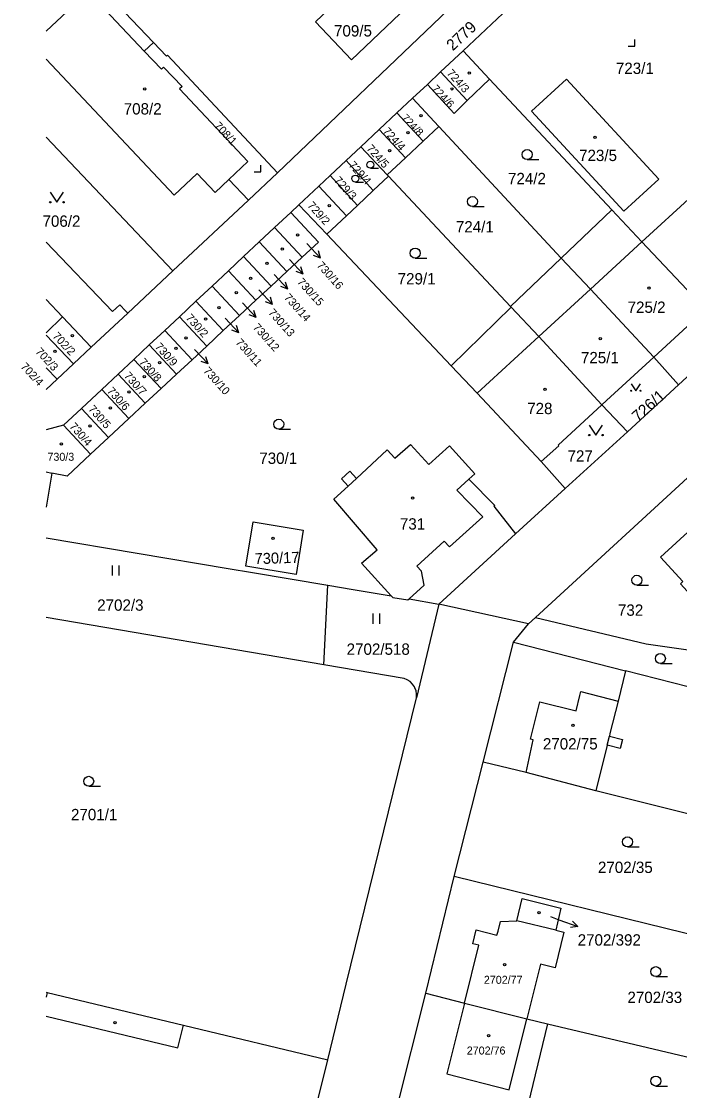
# Model space of a CAD drawing. Extents: x -496682 to -495776, y -1088797 to -1088018.
# Drawn here: x -496677.9 to -496579.2, y -1088379.3 to -1088218.9 of the extents above; entities that cross this region are included whole.
import ezdxf

# ---------------------------------------------------------------- set-up
doc = ezdxf.new("R2010")
doc.units = 0
for name, color, linetype in [('Hranice parcel', 7, 'Continuous'), ('Parcelní čísla', 7, 'Continuous'), ('Pop  PČ popisy', 7, 'Continuous'), ('Vnitřní kresba', 7, 'Continuous'), ('Značky budov', 7, 'Continuous'), ('Značky kultur', 7, 'Continuous')]:
    doc.layers.add(name, color=color, linetype=linetype)

msp = doc.modelspace()

# ---------------------------------------------------------------- linework, layer by layer
at = {"layer": 'Hranice parcel'}
for p, q in [((-496658.12, -1088222.07), (-496674.2, -1088205.13)), ((-496598.99, -1088211.34), (-496611.67, -1088223.3)), ((-496613.98, -1088217.23), (-496639.51, -1088241.62)), ((-496658.12, -1088222.07), (-496659.48, -1088223.35)), ((-496611.67, -1088223.3), (-496615.08, -1088226.47)), ((-496611.67, -1088223.3), (-496607.69, -1088227.55)), ((-496617.01, -1088228.38), (-496615.08, -1088226.47)), ((-496615.08, -1088226.47), (-496611.06, -1088230.75)), ((-496607.69, -1088227.55), (-496611.06, -1088230.75)), ((-496607.69, -1088227.55), (-496589.37, -1088247.15)), ((-496617.01, -1088228.38), (-496619.25, -1088230.42)), ((-496621.61, -1088232.63), (-496619.25, -1088230.42)), ((-496619.25, -1088230.42), (-496615.3, -1088234.67)), ((-496621.61, -1088232.63), (-496624.27, -1088235.13)), ((-496617.64, -1088236.86), (-496621.61, -1088232.63)), ((-496624.27, -1088235.13), (-496627.02, -1088237.7)), ((-496624.27, -1088235.13), (-496620.31, -1088239.36)), ((-496615.3, -1088234.67), (-496617.64, -1088236.86)), ((-496596.95, -1088254.39), (-496615.3, -1088234.67)), ((-496617.64, -1088236.86), (-496620.31, -1088239.36)), ((-496627.02, -1088237.7), (-496629.21, -1088239.75)), ((-496627.02, -1088237.7), (-496623.05, -1088241.94)), ((-496629.21, -1088239.75), (-496631.61, -1088242.01)), ((-496625.14, -1088244.28), (-496629.21, -1088239.75)), ((-496620.31, -1088239.36), (-496623.05, -1088241.94)), ((-496643.86, -1088245.72), (-496639.51, -1088241.62)), ((-496627.51, -1088246.52), (-496631.61, -1088242.01)), ((-496622.86, -1088242.14), (-496625.14, -1088244.28)), ((-496623.05, -1088241.94), (-496622.86, -1088242.14)), ((-496622.86, -1088242.14), (-496604.56, -1088261.65)), ((-496646.82, -1088242.63), (-496643.86, -1088245.72)), ((-496625.14, -1088244.28), (-496627.51, -1088246.52)), ((-496643.86, -1088245.72), (-496655.18, -1088256.3)), ((-496636.3, -1088246.41), (-496637.53, -1088247.57)), ((-496636.3, -1088246.41), (-496632.12, -1088250.83)), ((-496596.95, -1088254.39), (-496589.37, -1088247.15)), ((-496589.37, -1088247.15), (-496584.85, -1088251.98)), ((-496637.53, -1088247.57), (-496639.96, -1088249.83)), ((-496639.96, -1088249.83), (-496642.25, -1088251.98)), ((-496635.82, -1088254.27), (-496639.96, -1088249.83)), ((-496642.25, -1088251.98), (-496644.6, -1088254.18)), ((-496638.12, -1088256.41), (-496642.25, -1088251.98)), ((-496632.12, -1088250.83), (-496613.46, -1088270.55)), ((-496584.85, -1088251.98), (-496575.3, -1088262.11)), ((-496644.6, -1088254.18), (-496646.86, -1088256.3)), ((-496640.47, -1088258.61), (-496644.6, -1088254.18)), ((-496635.82, -1088254.27), (-496638.12, -1088256.41)), ((-496604.56, -1088261.65), (-496596.95, -1088254.39)), ((-496655.18, -1088256.3), (-496661.97, -1088262.66)), ((-496646.86, -1088256.3), (-496649.3, -1088258.59)), ((-496642.74, -1088260.72), (-496646.86, -1088256.3)), ((-496638.12, -1088256.41), (-496640.47, -1088258.61)), ((-496649.3, -1088258.59), (-496651.74, -1088260.88)), ((-496645.23, -1088263.03), (-496649.3, -1088258.59)), ((-496640.47, -1088258.61), (-496642.74, -1088260.72)), ((-496651.74, -1088260.88), (-496654.22, -1088263.2)), ((-496647.64, -1088265.28), (-496651.74, -1088260.88)), ((-496642.74, -1088260.72), (-496645.23, -1088263.03)), ((-496674.2, -1088265.6), (-496671.74, -1088263.22)), ((-496667.44, -1088267.77), (-496671.74, -1088263.22)), ((-496667.44, -1088267.77), (-496661.97, -1088262.66)), ((-496654.22, -1088263.2), (-496656.41, -1088265.25)), ((-496654.22, -1088263.2), (-496650.13, -1088267.6)), ((-496645.23, -1088263.03), (-496647.64, -1088265.28)), ((-496604.44, -1088261.78), (-496613.46, -1088270.55)), ((-496604.56, -1088261.65), (-496604.44, -1088261.78)), ((-496583.08, -1088269.26), (-496575.3, -1088262.11)), ((-496674.2, -1088265.98), (-496670.08, -1088270.24)), ((-496656.41, -1088265.25), (-496658.75, -1088267.43)), ((-496652.33, -1088269.64), (-496656.41, -1088265.25)), ((-496647.64, -1088265.28), (-496650.13, -1088267.6)), ((-496579.39, -1088273.39), (-496571.63, -1088266.25)), ((-496670.08, -1088270.24), (-496667.44, -1088267.77)), ((-496658.75, -1088267.43), (-496661.05, -1088269.59)), ((-496654.67, -1088271.82), (-496658.75, -1088267.43)), ((-496650.13, -1088267.6), (-496652.33, -1088269.64)), ((-496661.05, -1088269.59), (-496663.42, -1088271.81)), ((-496656.97, -1088273.96), (-496661.05, -1088269.59)), ((-496652.33, -1088269.64), (-496654.67, -1088271.82)), ((-496579.39, -1088273.39), (-496583.08, -1088269.26)), ((-496674.2, -1088270.84), (-496672.55, -1088272.55)), ((-496672.55, -1088272.55), (-496670.08, -1088270.24)), ((-496674.2, -1088274.09), (-496672.55, -1088272.55)), ((-496663.42, -1088271.81), (-496665.86, -1088274.1)), ((-496659.35, -1088276.18), (-496663.42, -1088271.81)), ((-496654.67, -1088271.82), (-496656.97, -1088273.96)), ((-496665.86, -1088274.1), (-496668.89, -1088276.94)), ((-496661.8, -1088278.46), (-496665.86, -1088274.1)), ((-496656.97, -1088273.96), (-496659.35, -1088276.18)), ((-496587.04, -1088280.45), (-496579.39, -1088273.39)), ((-496668.89, -1088276.94), (-496671.59, -1088279.46)), ((-496664.84, -1088281.29), (-496668.89, -1088276.94)), ((-496659.35, -1088276.18), (-496661.8, -1088278.46)), ((-496590.86, -1088276.42), (-496587.04, -1088280.45)), ((-496661.8, -1088278.46), (-496664.84, -1088281.29)), ((-496671.59, -1088279.46), (-496674.2, -1088280.16)), ((-496667.54, -1088283.8), (-496671.59, -1088279.46)), ((-496596.36, -1088288.95), (-496587.04, -1088280.45)), ((-496664.84, -1088281.29), (-496667.54, -1088283.8)), ((-496573.69, -1088283.35), (-496600.82, -1088308.29)), ((-496599.99, -1088284.92), (-496596.36, -1088288.95)), ((-496674.2, -1088286.47), (-496673.36, -1088286.64)), ((-496673.36, -1088286.64), (-496674.2, -1088291.77)), ((-496603.81, -1088295.77), (-496596.36, -1088288.95)), ((-496615.31, -1088306.29), (-496603.81, -1088295.77)), ((-496632.58, -1088315.39), (-496631.97, -1088303.45)), ((-496615.31, -1088306.29), (-496618.66, -1088320.33)), ((-496601.85, -1088309.24), (-496615.31, -1088306.29)), ((-496632.58, -1088315.39), (-496674.2, -1088308.3)), ((-496604.09, -1088312.01), (-496601.85, -1088309.24)), ((-496600.82, -1088308.29), (-496601.85, -1088309.24)), ((-496608.66, -1088330.02), (-496604.09, -1088312.01)), ((-496604.09, -1088312.01), (-496587.31, -1088316.31)), ((-496620.51, -1088317.45), (-496632.58, -1088315.39)), ((-496558.12, -1088323.79), (-496587.31, -1088316.31)), ((-496629.19, -1088363.28), (-496618.66, -1088320.33)), ((-496613.01, -1088347.16), (-496608.66, -1088330.02)), ((-496562.31, -1088341.65), (-496591.79, -1088334.31)), ((-496617.24, -1088364.65), (-496613.01, -1088347.16)), ((-496566.3, -1088358.61), (-496613.01, -1088347.16)), ((-496597.79, -1088355.21), (-496603.63, -1088353.81)), ((-496631.98, -1088374.63), (-496629.19, -1088363.28)), ((-496621.61, -1088381.96), (-496617.24, -1088364.65)), ((-496617.24, -1088364.65), (-496611.47, -1088366.13)), ((-496611.47, -1088366.13), (-496602.12, -1088368.5)), ((-496602.12, -1088368.5), (-496599.03, -1088369.24)), ((-496599.03, -1088369.24), (-496603.2, -1088386.53)), ((-496599.03, -1088369.24), (-496570.63, -1088376)), ((-496640.68, -1088410.13), (-496631.98, -1088374.63))]:
    msp.add_line(p, q, dxfattribs=at)
for points in [[(-496624.78, -1088213.12), (-496628.32, -1088216.5), (-496629.71, -1088215.04), (-496633.83, -1088218.99), (-496628.4, -1088224.66), (-496618, -1088214.72), (-496620.89, -1088211.75), (-496623.61, -1088214.35), (-496624.78, -1088213.12)], [(-496659.48, -1088223.35), (-496667.9, -1088214.43), (-496674.2, -1088220.39)], [(-496567.11, -1088219.32), (-496576.33, -1088227.9), (-496569.52, -1088235.23), (-496571.03, -1088236.8), (-496569.79, -1088238.16), (-496584.85, -1088251.98)], [(-496639.51, -1088241.62), (-496655.99, -1088223.95), (-496656.16, -1088224.12), (-496658.12, -1088222.07)], [(-496674.2, -1088224.58), (-496654.99, -1088244.96), (-496651.56, -1088241.73), (-496648.88, -1088244.57), (-496646.82, -1088242.63)], [(-496659.48, -1088223.35), (-496656.91, -1088226.08), (-496656.58, -1088225.77), (-496653.83, -1088228.68), (-496654.21, -1088229.04), (-496643.95, -1088239.92), (-496646.82, -1088242.63)], [(-496582.32, -1088242.55), (-496587.57, -1088247.38), (-496601.4, -1088232.39), (-496596.18, -1088227.58), (-496582.32, -1088242.55)], [(-496611.06, -1088230.75), (-496612.99, -1088232.74), (-496617.01, -1088228.38)], [(-496674.2, -1088236.29), (-496655.18, -1088256.3)], [(-496631.61, -1088242.01), (-496633.32, -1088243.62), (-496636.3, -1088246.41)], [(-496627.51, -1088246.52), (-496629.16, -1088248.07), (-496632.12, -1088250.83)], [(-496637.53, -1088247.57), (-496633.38, -1088252), (-496635.82, -1088254.27)], [(-496661.97, -1088262.66), (-496662.3, -1088262.31), (-496663.16, -1088261.41), (-496664.23, -1088262.43), (-496674.2, -1088251.99)], [(-496583.08, -1088269.26), (-496592.58, -1088259.08), (-496596.95, -1088254.39)], [(-496671.74, -1088263.22), (-496674.2, -1088260.62)], [(-496604.44, -1088261.78), (-496600.31, -1088266.18), (-496590.86, -1088276.42)], [(-496590.86, -1088276.42), (-496590.17, -1088275.78), (-496583.08, -1088269.26)], [(-496613.46, -1088270.55), (-496609.56, -1088274.67), (-496599.99, -1088284.92)], [(-496590.86, -1088276.42), (-496597.43, -1088282.45), (-496597.33, -1088282.57), (-496599.99, -1088284.92)], [(-496622.44, -1088305.06), (-496626.89, -1088300.16), (-496624.57, -1088298.15), (-496631.04, -1088290.58), (-496628.89, -1088288.59), (-496629.91, -1088287.49), (-496628.67, -1088286.35), (-496627.66, -1088287.45), (-496623.04, -1088283.17), (-496621.92, -1088284.39), (-496619.54, -1088282.35), (-496616.81, -1088285.36), (-496613.73, -1088282.57), (-496609.93, -1088286.75), (-496610.83, -1088287.57), (-496606.92, -1088291.49), (-496607.06, -1088291.61), (-496603.81, -1088295.77)], [(-496667.54, -1088283.8), (-496671.07, -1088287.09), (-496673.36, -1088286.64)], [(-496557.01, -1088316.13), (-496563.54, -1088302.9), (-496571.78, -1088310.53), (-496575.32, -1088306.66), (-496575.68, -1088306.99), (-496579.09, -1088303.24), (-496578.73, -1088302.91), (-496582.06, -1088299.26), (-496577.39, -1088294.94), (-496577.72, -1088294.58), (-496573.95, -1088291.1), (-496573.62, -1088291.45), (-496569.64, -1088287.77), (-496570.83, -1088286.2), (-496573.69, -1088283.35)], [(-496636.73, -1088301.87), (-496644.24, -1088300.6), (-496643.15, -1088293.97), (-496635.64, -1088295.22), (-496636.73, -1088301.87)], [(-496674.2, -1088296.34), (-496646.9, -1088300.94), (-496643.26, -1088301.55), (-496631.97, -1088303.45)], [(-496631.97, -1088303.45), (-496628.18, -1088304.09), (-496622.44, -1088305.06)], [(-496622.44, -1088305.06), (-496622.2, -1088305.33), (-496619.97, -1088305.68), (-496619.76, -1088305.49), (-496615.31, -1088306.29)], [(-496600.82, -1088308.29), (-496584.23, -1088312.23), (-496557.01, -1088316.13)], [(-496618.66, -1088320.33), (-496618.64, -1088319.82), (-496618.71, -1088319.31), (-496618.89, -1088318.83), (-496618.96, -1088318.7), (-496619.24, -1088318.28), (-496619.61, -1088317.92), (-496620.04, -1088317.64), (-496620.51, -1088317.45)], [(-496587.31, -1088316.31), (-496588.44, -1088320.85), (-496589.65, -1088325.71), (-496589.74, -1088326.09), (-496587.78, -1088326.58), (-496588.11, -1088327.93), (-496590.08, -1088327.44), (-496591.79, -1088334.31)], [(-496591.79, -1088334.31), (-496602.19, -1088331.54), (-496608.66, -1088330.02)], [(-496603.63, -1088353.81), (-496602.83, -1088350.47), (-496597, -1088351.88), (-496597.79, -1088355.21)], [(-496611.47, -1088366.13), (-496609.31, -1088357.47), (-496610.23, -1088357.24), (-496609.71, -1088355.17), (-496606.59, -1088355.94), (-496606.43, -1088355.33), (-496606.05, -1088353.9), (-496603.63, -1088353.81)], [(-496597.79, -1088355.21), (-496596.58, -1088355.5), (-496597.86, -1088360.83), (-496600.06, -1088360.3), (-496602.12, -1088368.5)], [(-496674.2, -1088364.5), (-496674.03, -1088364.55), (-496653.61, -1088369.44), (-496631.98, -1088374.63)]]:
    msp.add_lwpolyline(points, dxfattribs=at)
at = {"layer": 'Pop  PČ popisy'}
for p, q in [((-496635.11, -1088252.19), (-496633.06, -1088254.39)), ((-496633.06, -1088254.39), (-496633.38, -1088253.31)), ((-496637.72, -1088254.6), (-496635.67, -1088256.79)), ((-496633.06, -1088254.39), (-496634.11, -1088253.99)), ((-496635.67, -1088256.79), (-496636.72, -1088256.4)), ((-496635.67, -1088256.79), (-496635.99, -1088255.72)), ((-496640.02, -1088256.88), (-496637.97, -1088259.07)), ((-496637.97, -1088259.07), (-496638.29, -1088258)), ((-496642.31, -1088259.15), (-496640.26, -1088261.34)), ((-496637.97, -1088259.07), (-496639.02, -1088258.68)), ((-496644.77, -1088261.13), (-496642.72, -1088263.32)), ((-496640.26, -1088261.34), (-496641.31, -1088260.95)), ((-496640.26, -1088261.34), (-496640.58, -1088260.27)), ((-496642.72, -1088263.32), (-496643.77, -1088262.93)), ((-496642.72, -1088263.32), (-496643.04, -1088262.25)), ((-496647.37, -1088263.4), (-496645.32, -1088265.59)), ((-496645.32, -1088265.59), (-496645.64, -1088264.52)), ((-496645.32, -1088265.59), (-496646.37, -1088265.2)), ((-496651.97, -1088268.09), (-496649.92, -1088270.28)), ((-496649.92, -1088270.28), (-496650.24, -1088269.21)), ((-496649.92, -1088270.28), (-496650.97, -1088269.89)), ((-496598.58, -1088353.17), (-496597.3, -1088353.64)), ((-496597.3, -1088353.64), (-496594.48, -1088354.67)), ((-496594.48, -1088354.67), (-496595.25, -1088353.85)), ((-496594.48, -1088354.67), (-496595.59, -1088354.79))]:
    msp.add_line(p, q, dxfattribs=at)
at = {"layer": 'Vnitřní kresba'}
for p, q in [((-496633.32, -1088243.62), (-496629.16, -1088248.07)), ((-496592.58, -1088259.08), (-496584.85, -1088251.98)), ((-496600.31, -1088266.18), (-496592.58, -1088259.08)), ((-496609.56, -1088274.67), (-496600.31, -1088266.18)), ((-496627.66, -1088287.45), (-496628.89, -1088288.59)), ((-496612.62, -1088289.19), (-496610.83, -1088287.57)), ((-496608.71, -1088293.21), (-496612.62, -1088289.19)), ((-496613.73, -1088297.7), (-496608.71, -1088293.21)), ((-496618.63, -1088300.61), (-496614.51, -1088296.84)), ((-496614.51, -1088296.84), (-496613.73, -1088297.7)), ((-496617.93, -1088301.38), (-496618.63, -1088300.61)), ((-496617.51, -1088303.44), (-496617.93, -1088301.38)), ((-496619.76, -1088305.49), (-496617.51, -1088303.44)), ((-496601.58, -1088326.57), (-496600.18, -1088320.97)), ((-496600.18, -1088320.97), (-496594.74, -1088322.29)), ((-496594.74, -1088322.29), (-496594.15, -1088319.98)), ((-496594.15, -1088319.98), (-496594.01, -1088319.42)), ((-496594.01, -1088319.42), (-496588.44, -1088320.85)), ((-496602.19, -1088331.54), (-496601.19, -1088326.65)), ((-496601.19, -1088326.65), (-496601.58, -1088326.57)), ((-496590.08, -1088327.44), (-496589.74, -1088326.09)), ((-496674.03, -1088364.55), (-496674.2, -1088365.27)), ((-496611.47, -1088366.13), (-496614.11, -1088376.73)), ((-496674.2, -1088368.11), (-496654.44, -1088372.82)), ((-496604.78, -1088379.15), (-496602.12, -1088368.5)), ((-496654.44, -1088372.82), (-496653.61, -1088369.44)), ((-496614.11, -1088376.73), (-496604.78, -1088379.15))]:
    msp.add_line(p, q, dxfattribs=at)
at = {"layer": 'Značky budov'}
for centre in [(-496610.74, -1088226.65), (-496659.42, -1088229.03), (-496613.34, -1088229.02), (-496617.98, -1088233.05), (-496619.94, -1088235.59), (-496591.88, -1088236.3), (-496622.7, -1088238.29), (-496631.75, -1088246.52), (-496636.5, -1088250.92), (-496638.8, -1088253.04), (-496641.1, -1088255.17), (-496643.55, -1088257.44), (-496645.7, -1088259.57), (-496583.8, -1088258.89), (-496648.3, -1088261.84), (-496650.3, -1088263.54), (-496670.26, -1088266.02), (-496653.21, -1088266.38), (-496591.1, -1088266.49), (-496654.74, -1088267.94), (-496672.88, -1088268.4), (-496657.2, -1088270.07), (-496659.5, -1088272.2), (-496661.8, -1088274.47), (-496599.38, -1088274.1), (-496664.56, -1088276.88), (-496667.62, -1088279.58), (-496671.92, -1088282.28), (-496619.24, -1088290.39), (-496640.16, -1088296.42), (-496595.2, -1088324.47), (-496600.28, -1088352.55), (-496605.45, -1088360.35), (-496663.86, -1088369.08), (-496607.85, -1088371.04)]:
    msp.add_circle(centre, 0.175, dxfattribs=at)
at = {"layer": 'Značky kultur'}
for p, q in [((-496586.9, -1088222.63), (-496585.9, -1088222.63)), ((-496585.9, -1088222.63), (-496585.9, -1088221.63)), ((-496642.03, -1088241.45), (-496642.03, -1088240.45)), ((-496602.06, -1088239.63), (-496600.31, -1088239.63)), ((-496643.03, -1088241.45), (-496642.03, -1088241.45)), ((-496625.57, -1088240.93), (-496624.34, -1088240.93)), ((-496627.82, -1088243.01), (-496626.59, -1088243.01)), ((-496610.27, -1088246.68), (-496608.52, -1088246.68)), ((-496618.86, -1088254.4), (-496617.11, -1088254.4)), ((-496639.32, -1088280.07), (-496637.57, -1088280.07)), ((-496664.27, -1088301.99), (-496664.27, -1088300.49)), ((-496663.27, -1088301.99), (-496663.27, -1088300.49)), ((-496585.61, -1088303.47), (-496583.86, -1088303.47)), ((-496625.15, -1088309.23), (-496625.15, -1088307.73)), ((-496624.15, -1088309.23), (-496624.15, -1088307.73)), ((-496582.09, -1088315.2), (-496580.34, -1088315.2)), ((-496667.82, -1088333.62), (-496666.07, -1088333.62)), ((-496587.02, -1088342.71), (-496585.27, -1088342.71)), ((-496582.77, -1088362.17), (-496581.02, -1088362.17)), ((-496582.77, -1088378.57), (-496581.02, -1088378.57))]:
    msp.add_line(p, q, dxfattribs=at)
for points in [[(-496673.59, -1088244.53), (-496672.59, -1088246.03), (-496671.59, -1088244.53)], [(-496586.46, -1088273.25), (-496585.76, -1088274.3), (-496585.06, -1088273.25)], [(-496592.75, -1088279.45), (-496591.75, -1088280.95), (-496590.75, -1088279.45)]]:
    msp.add_lwpolyline(points, dxfattribs=at)
for centre, radius in [((-496602.06, -1088238.88), 0.75), ((-496625.57, -1088240.4), 0.525), ((-496627.82, -1088242.48), 0.525), ((-496610.27, -1088245.93), 0.75), ((-496673.59, -1088246.03), 0.1), ((-496671.59, -1088246.03), 0.1), ((-496618.86, -1088253.65), 0.75), ((-496586.46, -1088274.3), 0.07), ((-496585.06, -1088274.3), 0.07), ((-496639.32, -1088279.32), 0.75), ((-496592.75, -1088280.95), 0.1), ((-496590.75, -1088280.95), 0.1), ((-496585.61, -1088302.72), 0.75), ((-496582.09, -1088314.45), 0.75), ((-496667.82, -1088332.87), 0.75), ((-496587.02, -1088341.96), 0.75), ((-496582.77, -1088361.42), 0.75), ((-496582.77, -1088377.82), 0.75)]:
    msp.add_circle(centre, radius, dxfattribs=at)

# ---------------------------------------------------------------- texts
at = {"layer": 'Parcelní čísla'}
for s, height, p in [('709/5', 1.7, (-496631.03, -1088221.17)), ('723/1', 1.7, (-496588.76, -1088226.79)), ('708/2', 1.7, (-496662.57, -1088232.87)), ('723/5', 1.7, (-496594.28, -1088239.85)), ('724/2', 1.7, (-496604.94, -1088243.32)), ('706/2', 1.7, (-496674.75, -1088249.71)), ('724/1', 1.7, (-496612.76, -1088250.56)), ('729/1', 1.7, (-496621.49, -1088258.35)), ('725/2', 1.7, (-496587, -1088262.62)), ('725/1', 1.7, (-496594, -1088270.18)), ('728', 1.7, (-496602.06, -1088277.81)), ('730/3', 1.2, (-496674.01, -1088284.8)), ('730/1', 1.7, (-496642.24, -1088285.27)), ('727', 1.7, (-496596.01, -1088284.93)), ('731', 1.7, (-496621.16, -1088295.12)), ('2702/3', 1.7, (-496666.55, -1088307.29)), ('732', 1.7, (-496588.45, -1088308.05)), ('2702/518', 1.7, (-496629.14, -1088313.9)), ('2702/75', 1.7, (-496599.71, -1088328.1)), ('2701/1', 1.7, (-496670.48, -1088338.71)), ('2702/35', 1.7, (-496591.45, -1088346.62)), ('2702/392', 1.7, (-496594.49, -1088357.51)), ('2702/77', 1.2, (-496608.56, -1088363.24)), ('2702/33', 1.7, (-496587.03, -1088366.12)), ('2702/76', 1.2, (-496611.12, -1088373.85))]:
    msp.add_text(s, height=height, dxfattribs=at).set_placement(p)
for s, height, rotation, p in [('2779', 1.7, 43, (-496613.22, -1088223.41)), ('724/3', 1.2, 312, (-496614.2, -1088226.74)), ('724/6', 1.199, 313, (-496616.5, -1088229.09)), ('724/8', 1.139, 314, (-496620.97, -1088233.47)), ('708/1', 1.2, 313, (-496649.09, -1088234.65)), ('724/4', 1.2, 312, (-496623.78, -1088235.44)), ('724/5', 1.2, 312, (-496626.24, -1088238.04)), ('729/4', 1.2, 312, (-496628.92, -1088240.53)), ('729/3', 1.2, 312, (-496631.1, -1088242.81)), ('729/2', 1.2, 312, (-496635.1, -1088246.58)), ('730/16', 1.2, 312, (-496633.7, -1088255.56)), ('730/15', 1.2, 312, (-496636.63, -1088258.05)), ('730/14', 1.2, 312, (-496638.6, -1088260.39)), ('730/2', 1.2, 312, (-496653.35, -1088263.44)), ('730/13', 1.2, 312, (-496640.98, -1088262.66)), ('730/12', 1.2, 312, (-496643.27, -1088264.86)), ('702/2', 1.2, 313, (-496673.32, -1088266.18)), ('730/11', 1.2, 312, (-496645.88, -1088267.13)), ('702/3', 1.2, 313, (-496675.89, -1088268.51)), ('730/9', 1.2, 312, (-496657.96, -1088267.76)), ('730/8', 1.2, 312, (-496660.35, -1088270.08)), ('702/4', 1.2, 313, (-496678.11, -1088270.75)), ('730/10', 1.2, 312, (-496650.71, -1088271.38)), ('730/7', 1.2, 312, (-496662.61, -1088272.13)), ('730/6', 1.2, 312, (-496665.14, -1088274.4)), ('726/1', 1.7, 42, (-496585.43, -1088279.07)), ('730/5', 1.2, 312, (-496667.96, -1088277.12)), ('730/4', 1.2, 312, (-496670.79, -1088279.72)), ('730/17', 1.643, 2, (-496642.91, -1088300.32))]:
    msp.add_text(s, height=height, rotation=rotation, dxfattribs=at).set_placement(p)

doc.saveas('drawing.dxf')
